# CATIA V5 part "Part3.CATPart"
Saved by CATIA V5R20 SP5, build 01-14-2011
Part number: Part3
Material "Brass": density 8216 kg/m3, Young's modulus 1.31e+11 Pa, Poisson ratio 0.35, thermal expansion 1.67e-05 1/K
Bounding box of the stored display mesh (mm): x -30.659 to 29.745, y -32.138 to 25, z -126.413 to 50
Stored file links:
  E:\180511232\Part3.CATPart
  C:\Program Files\Dassault Systemes\B20\intel_a\startup\materials\Catalog.CATMaterial
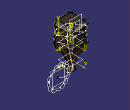
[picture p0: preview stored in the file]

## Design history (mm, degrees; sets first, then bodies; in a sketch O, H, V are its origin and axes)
Set1
  Sketch1 on xy-plane, origin (0, 0, 0), H (1, 0, 0), V (0, 1, 0)
    line L1 (25, 25) -> (25, -25)
    line L2 (25, -25) -> (-25, -25)
    line L3 (-25, -25) -> (-25, 25)
    line L4 (-25, 25) -> (25, 25)
    length L4 = 50
    length L1 = 50
    vertical: L1 V, L3 V
    horizontal: L2 H, L4 H
    equidistance: L1 L3 O, L2 L4 O
  Sketch2 on face of Pad1 from Sketch1.L3, origin (-25, 0, 0), H (0, -1, 0), V (0, 0, 1)
    spline S1 through (-42.1157, 18.4827) (-11.1794, 31.201) (8.2754, 22.6162) (38.5738, 31.201)
  Extrude1: Lim1 53, Lim2 53, Element1 Sketch2
  MultiSel1: CommonCtxFeats ({extract ExtractElem face of Pad1 from Sketch1.L3}; {extract ExtractElem face of Fillet1}; {extract ExtractElem face of Pad1 from Sketch1.L4}; {extract ExtractElem face of Fillet1}; {extract ExtractElem face of Pad1 from Sketch1.L1}; {extract ExtractElem face of Fillet1}; {extract ExtractElem face of Pad1 from Sketch1.L2}; {extract ExtractElem face of Fillet1})
  Sketch3 on face of Pad1 from Sketch1.L1, origin (25, 0, 0), H (0, 1, 0), V (0, 0, 1)
    spline S1 through (-35.6508, 14.5425) (-12.1043, 6.1379) (11.1515, 14.5425) (28.8841, 14.5425)
  Extrude2: Lim1 65, Lim2 65, Element1 Sketch3
  MultiSel2: CommonCtxFeats ({extract ExtractElem face of Pad1 from Sketch1.L1}; {extract ExtractElem face of Fillet1}; {extract ExtractElem face of Pad1 from Sketch1.L2}; {extract ExtractElem face of Fillet1}; {extract ExtractElem face of Pad1 from Sketch1.L3}; {extract ExtractElem face of Fillet1}; {extract ExtractElem face of Pad1 from Sketch1.L4}; {extract ExtractElem face of Fillet1})
  Join1: Elements ({intersect ToIntersect1 {extract ExtractElem face of Fillet1}, ToIntersect2 Extrude1}; {intersect ToIntersect1 {extract ExtractElem face of Pad1 from Sketch1.L4}, ToIntersect2 Extrude1}; {intersect ToIntersect1 {extract ExtractElem face of Fillet1}, ToIntersect2 Extrude1}; {intersect ToIntersect1 {extract ExtractElem face of Pad1 from Sketch1.L1}, ToIntersect2 Extrude1}; {intersect ToIntersect1 {extract ExtractElem face of Fillet1}, ToIntersect2 Extrude1}; {intersect ToIntersect1 {extract ExtractElem face of Pad1 from Sketch1.L2}, ToIntersect2 Extrude1}; {intersect ToIntersect1 {extract ExtractElem face of Fillet1}, ToIntersect2 Extrude1}; {intersect ToIntersect1 {extract ExtractElem face of Pad1 from Sketch1.L3}, ToIntersect2 Extrude1})
  Plane1: type OffsetPt, RefPlane face of Pad1 from Sketch1.L2, RefPoint vertex of MultiSel2
  Circle1: type CtrRad, Start 0, End 180, Radius 1, Center vertex of MultiSel2, Support Plane1, FirstDirection (-1, 0, 0)
  Plane2: type OffsetPt, RefPlane face of Pad1 from Sketch1.L2, RefPoint vertex [face of MultiSel1 | face of MultiSel1]
  Circle2: type CtrRad, Start 0, End 180, Radius 1, Center vertex [face of MultiSel1 | face of MultiSel1], Support Plane2, FirstDirection (-1, 0, 0)
Body1 (main body), material "Brass"
  Pad1: profile Sketch1, direction (0, 0, 1), length 50
  Fillet1: on edge [face of Pad1 from Sketch1.L4 | face of Pad1 from Sketch1.L1]; edge [face of Pad1 from Sketch1.L3 | face of Pad1 from Sketch1.L4]; edge [face of Pad1 from Sketch1.L1 | face of Pad1 from Sketch1.L2]; edge [face of Pad1 from Sketch1.L2 | face of Pad1 from Sketch1.L3]
  Fillet2: radius 8, on end face of Pad1
  Plane3: type Offset, RefPlane xy-plane, Offset 40, reversed
  Sketch4 on Plane3, origin (0, 0, -40), H (1, 0, 0), V (0, 1, 0)
  Sketch5 on Plane3, origin (0, 0, -40), H (1, 0, 0), V (0, 1, 0)
    circle A1 centre (0, 0) radius 10
    radius A1 = 10
  Sketch6 on start face of Pad1, origin (0, 0, 0), H (1, 0, 0), V (0, -1, 0)
    reference projected line E1 (-25, -25) -> (-25, 25) from edge [start face of Pad1 | face of Pad1 from Sketch1.L3]
    distance E1 O = 25
  Pad2: profile Sketch5, direction (0, 0, -1), length 20
  Sketch7 on start face of Pad1, origin (0, 0, 0), H (1, 0, 0), V (0, -1, 0)
    point P1 (25, 0)
    distance P1 O = 25
    coincidence: P1 H
  Sketch8 on Plane3, origin (0, 0, -40), H (1, 0, 0), V (0, 1, 0)
    point P1 (25, 0)
    distance P1 O = 25
    coincidence: P1 H
  Sketch9 on start face of Pad2, origin (0, 0, -40), H (1, 0, 0), V (0, 1, 0)
    point P1 (10, 0)
    distance P1 O = 10
    coincidence: P1 H
  Loft1: solid, Sections ({boundary Boundary {extract ExtractElem start face of Pad2}}; {boundary Boundary {extract ExtractElem start face of Pad1}}), StartFace start face of Pad2, EndFace start face of Pad1
  Slot1: profile Circle1, centre curve {join Elements ({intersect ToIntersect2 Extrude2}; {intersect ToIntersect2 Extrude2}; {intersect ToIntersect2 Extrude2}; {intersect ToIntersect2 Extrude2}; {intersect ToIntersect2 Extrude2}; {intersect ToIntersect2 Extrude2}; {intersect ToIntersect2 Extrude2}; {intersect ToIntersect2 Extrude2})}
  Slot2: profile Circle2, centre curve {join Elements ({intersect ToIntersect2 Extrude1}; {intersect ToIntersect2 Extrude1}; {intersect ToIntersect2 Extrude1}; {intersect ToIntersect2 Extrude1}; {intersect ToIntersect2 Extrude1}; {intersect ToIntersect2 Extrude1}; {intersect ToIntersect2 Extrude1}; {intersect ToIntersect2 Extrude1})}
  Shell1: ExtOffset 0, Face end face of Pad2, IntOffset 2
Body2
  Sketch10 on yz-plane, origin (0, 0, 0), H (0, 1, 0), V (0, 0, 1)
    spline S1 through (7.7653, 43.058) (-8.241, -6.3876) (3.031, -44.8204) (-32.1377, -96.0641)
  Plane4: type Tangent, Support face of Loft1, RefPoint vertex of Sketch10
  Sketch11 on Plane4, origin (0, -32.1377, 0), H (-1, 0, 0), V (0, 0, 1)
    circle A1 centre (0, -96.2369) radius 23.7209
    point P1 (0, -96.2369)
    point P2 (0, -119.9578)
    arc A2 centre (10.8671, -120.7863) radius 5.7071 from (5.3443, -119.3479) to (13.5155, -115.7308) ccw
    point P4 (5.3443, -119.3479)
    point P5 (13.5155, -115.7308)
    arc A3 centre (18.8282, -114.0007) radius 5.5874 from (13.5155, -115.7308) to (20.2466, -108.5963) ccw
    point P7 (20.2466, -108.5963)
    arc A4 centre (24.3156, -104.1657) radius 6.0155 from (20.2466, -108.5963) to (23.6405, -98.1882) ccw
    point P9 (20.2466, -108.5963)
    point P10 (23.6405, -98.1882)
    arc A5 centre (25.211, -92.6624) radius 5.5604 from (24.3156, -98.1502) to (22.2326, -87.967) ccw
    point P12 (24.3156, -98.1502)
    point P13 (22.2326, -87.967)
    arc A6 centre (20.0132, -82.4453) radius 5.951 from (22.2326, -87.967) to (15.6435, -78.4055) ccw
    point P15 (15.6435, -78.4055)
    arc A7 centre (0.5555, -121.1349) radius 5.1113 from (5.3443, -119.3479) to (-4.5438, -120.7863) cw
    point P17 (-4.5438, -120.7863)
    arc A8 centre (-10.7081, -118.964) radius 6.428 from (-4.3081, -119.5633) to (-15.2449, -114.4103) cw
    point P19 (-4.3081, -119.5633)
    point P20 (-15.2449, -114.4103)
    arc A9 centre (-19.8702, -109.7679) radius 6.5533 from (-15.2449, -114.4103) to (-23.7782, -104.5073) cw
    arc A10 centre (-24.5825, -98.9885) radius 5.211 from (-22.4952, -103.7633) to (-23.7782, -93.8399) cw
    point P24 (-22.4952, -103.7633)
    arc A11 centre (-23.4301, -87.9662) radius 5.8841 from (-23.7782, -93.8399) to (-19.8702, -83.2811) cw
    point P27 (-19.8702, -83.2811)
    arc A12 centre (-14.9012, -79.6087) radius 6.1788 from (-19.8702, -83.2811) to (-10.7081, -75.0705) cw
    point P29 (-10.7081, -75.0705)
    arc A13 centre (-5.6318, -72.6291) radius 5.6329 from (-10.7081, -75.0705) to (0, -72.5161) cw
    point P31 (0, -72.5161)
    arc A14 centre (5.2874, -70.6554) radius 5.6053 from (0, -72.5161) to (9.404, -74.4598) cw
    point P33 (9.404, -74.4598)
    arc A15 centre (14.2946, -73.6323) radius 4.9601 from (9.404, -74.4598) to (15.6435, -78.4055) cw
    point P35 (9.404, -74.4598)
    coincidence: P1 V, A1 P2, P2 V, P4 A1, P5 A1, P7 A1, P9 A3, P10 A1, P12 A4, P13 A1, P15 A1, P19 A7, P19 A1, P20 A1, A8 P17, P24 A9, P24 A1, P27 A1, P29 A1, P31 A1, P31 V, P33 A1, P35 A14, P35 A1
    tangency: A9 A8, A10 A9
